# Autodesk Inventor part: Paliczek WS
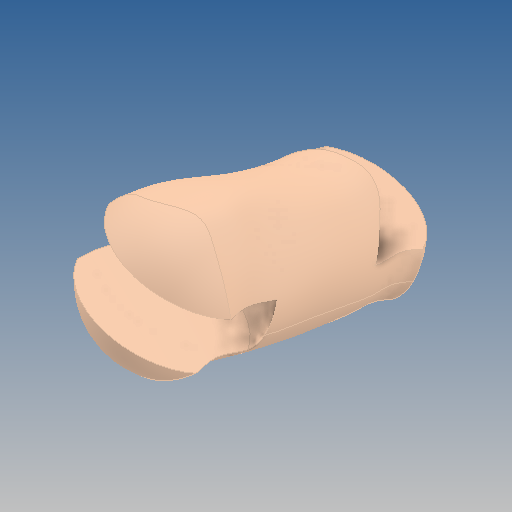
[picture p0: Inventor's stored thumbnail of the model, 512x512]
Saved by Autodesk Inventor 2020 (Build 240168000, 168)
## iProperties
Created: 2019-10
Part Number: Paliczek WS
Material: GFRP
Document SubType Name: Modeling
Designer: yello
Density: 1.75 g/cm^3
Appearance: Default
Author: yello
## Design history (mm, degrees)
feature "Paliczek WS"
body "Solid1"
